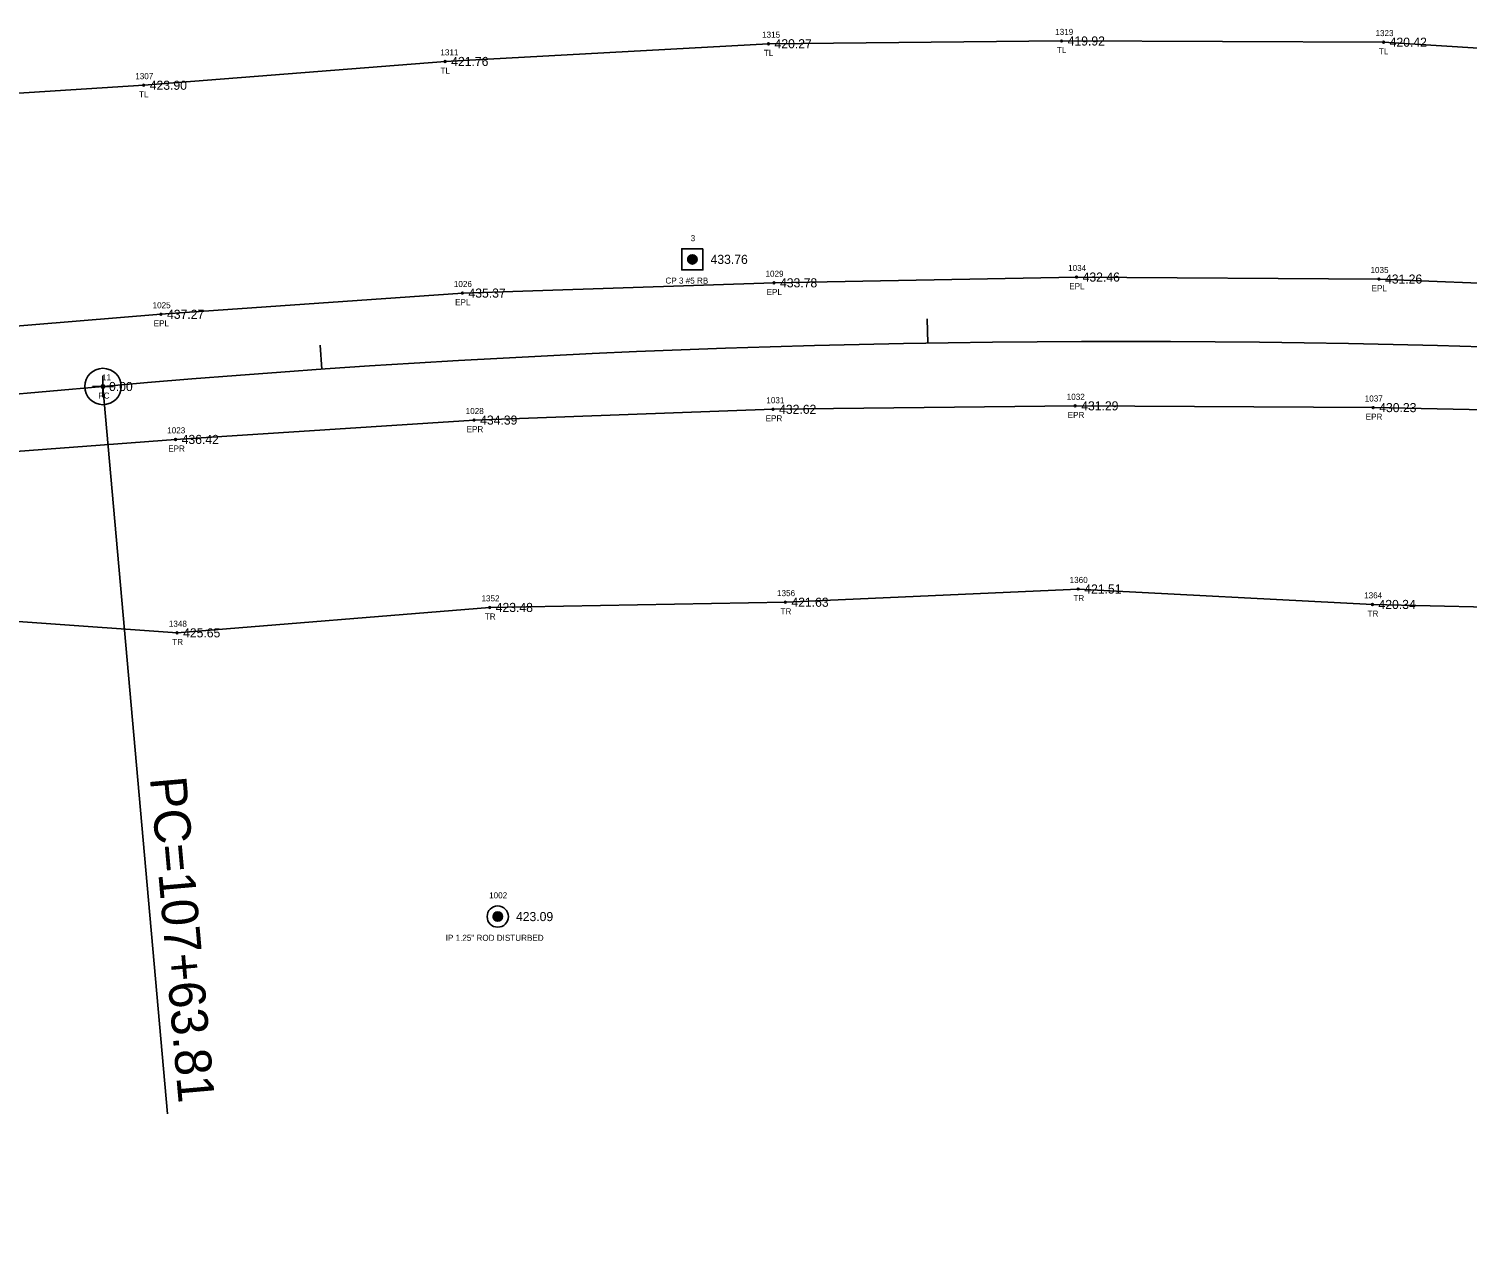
# Model space of a CAD drawing. Extents: x 1611114 to 1617038, y 769445 to 772083.
# Drawn here: x 1613520.1 to 1613757.2, y 771205.5 to 771408.3 of the extents above; entities that cross this region are included whole.
import ezdxf

# ---------------------------------------------------------------- set-up
doc = ezdxf.new("R2010")
doc.units = 0
for name, color, linetype in [('Default', 7, 'Continuous'), ('RD_EX_DV_Prop_txCode', 7, 'Continuous'), ('RD_EX_DV_PropPin', 7, 'Continuous'), ('RD_EX_Road', 7, 'Continuous'), ('RD_EX_Road_txCode', 7, 'Continuous'), ('RD_EX_TX_DV_Prop_ELEV', 7, 'Continuous'), ('RD_EX_TX_Road_ELEV', 7, 'Continuous'), ('RD_EX_TX_VEG_ELEV', 7, 'Continuous'), ('RD_EX_VEG', 7, 'Continuous'), ('RD_EX_VEG_txCode', 7, 'Continuous'), ('RD_HC_Cl', 7, 'Continuous'), ('RD_HC_Data', 7, 'Continuous'), ('RD_HC_Data_Tic', 7, 'Continuous'), ('RD_HC_Survey', 7, 'Continuous'), ('RD_HC_Survey_ELEV', 7, 'Continuous'), ('RD_HC_Survey_txCode', 7, 'Continuous'), ('RD_HC_txCode', 7, 'Continuous'), ('RD_SMD_Locator', 7, 'Continuous')]:
    doc.layers.add(name, color=color, linetype=linetype)

msp = doc.modelspace()

# ---------------------------------------------------------------- linework, layer by layer
at = {"layer": 'Default'}
for p, q in [((1612970.69, 771299.55), (1613532.3, 771349.3)), ((1613534.05, 771349.3), (1613530.55, 771349.3)), ((1613532.3, 771351.05), (1613532.3, 771347.55))]:
    msp.add_line(p, q, dxfattribs=at)
msp.add_arc((1613700.84, 769446.93), 1909.82, 80.96676, 95.06271, dxfattribs=at)
msp.add_arc((1613700.84, 769446.93), 1909.82, 80.96676, 95.06271, dxfattribs=at)
at = {"layer": 'RD_EX_DV_PropPin'}
for p, q in [((1613596.65, 771261.68), (1613596.65, 771262.07)), ((1613596.69, 771261.58), (1613596.69, 771262.17)), ((1613596.72, 771261.5), (1613596.72, 771262.24)), ((1613596.76, 771261.45), (1613596.76, 771262.3)), ((1613596.79, 771261.4), (1613596.79, 771262.35)), ((1613596.83, 771261.36), (1613596.83, 771262.39)), ((1613596.86, 771261.32), (1613596.86, 771262.42)), ((1613596.9, 771261.29), (1613596.9, 771262.46)), ((1613596.93, 771261.26), (1613596.93, 771262.48)), ((1613596.97, 771261.24), (1613596.97, 771262.51)), ((1613597, 771261.22), (1613597, 771262.53)), ((1613597.04, 771261.2), (1613597.04, 771262.55)), ((1613597.07, 771261.18), (1613597.07, 771262.57)), ((1613597.11, 771261.17), (1613597.11, 771262.58)), ((1613597.14, 771261.15), (1613597.14, 771262.59)), ((1613597.18, 771261.14), (1613597.18, 771262.6)), ((1613597.21, 771261.13), (1613597.21, 771262.61)), ((1613597.25, 771261.13), (1613597.25, 771262.62)), ((1613597.28, 771261.12), (1613597.28, 771262.63)), ((1613597.32, 771261.12), (1613597.32, 771262.63)), ((1613597.35, 771261.11), (1613597.35, 771262.63)), ((1613597.39, 771261.11), (1613597.39, 771262.63)), ((1613597.42, 771261.11), (1613597.42, 771262.63)), ((1613597.46, 771261.12), (1613597.46, 771262.63)), ((1613597.49, 771261.12), (1613597.49, 771262.63)), ((1613597.53, 771261.13), (1613597.53, 771262.62)), ((1613597.56, 771261.13), (1613597.56, 771262.61)), ((1613597.6, 771261.14), (1613597.6, 771262.6)), ((1613597.63, 771261.15), (1613597.63, 771262.59)), ((1613597.67, 771261.17), (1613597.67, 771262.58)), ((1613597.7, 771261.18), (1613597.7, 771262.57)), ((1613597.74, 771261.2), (1613597.74, 771262.55)), ((1613597.77, 771261.22), (1613597.77, 771262.53)), ((1613597.81, 771261.24), (1613597.81, 771262.51)), ((1613597.84, 771261.26), (1613597.84, 771262.48)), ((1613597.88, 771261.29), (1613597.88, 771262.46)), ((1613597.91, 771261.32), (1613597.91, 771262.42)), ((1613597.95, 771261.36), (1613597.95, 771262.39)), ((1613597.98, 771261.4), (1613597.98, 771262.35)), ((1613598.02, 771261.45), (1613598.02, 771262.3)), ((1613598.05, 771261.5), (1613598.05, 771262.24)), ((1613598.09, 771261.58), (1613598.09, 771262.17)), ((1613598.12, 771261.68), (1613598.12, 771262.07))]:
    msp.add_line(p, q, dxfattribs=at)
for radius in [1.75, 0.761]:
    msp.add_circle((1613597.39, 771261.87), radius, dxfattribs=at)
at = {"layer": 'RD_EX_Road'}
for points in [[(1613192.48, 771329.15), (1613292.05, 771338.23), (1613391, 771348.45), (1613492.61, 771357.17), (1613541.86, 771361.21), (1613591.56, 771364.71), (1613642.92, 771366.4), (1613692.81, 771367.35), (1613742.66, 771367.02), (1613792.19, 771365.04), (1613843.32, 771361.63), (1613887.78, 771357.57), (1613892.3, 771358.63)], [(1613194.6, 771309.27), (1613294.55, 771318.15), (1613393.75, 771328.31), (1613493.74, 771336.74), (1613544.27, 771340.57), (1613593.48, 771343.76), (1613642.77, 771345.54), (1613692.58, 771346.11), (1613741.71, 771345.82), (1613791.79, 771344.79), (1613840.79, 771341.46), (1613889.25, 771335.84)]]:
    msp.add_lwpolyline(points, dxfattribs=at)
at = {"layer": 'RD_EX_VEG'}
for points in [[(1613190.16, 771350.86), (1613289.21, 771359.12), (1613387.94, 771369.51), (1613489.82, 771379.95), (1613503.78, 771396.75), (1613539.01, 771398.99), (1613588.71, 771402.91), (1613642.02, 771405.83), (1613690.35, 771406.29), (1613743.43, 771406.09), (1613794.76, 771402.87), (1613849.1, 771400.75), (1613898.57, 771402.5), (1614071.38, 771363.76), (1614171, 771346.54), (1614270.56, 771328.42), (1614365.98, 771308.81), (1614467.36, 771290.78), (1614565.75, 771274.12), (1614666.78, 771259.85)], [(1613196.47, 771290.95), (1613297.34, 771299.06), (1613395.35, 771312.89), (1613495.9, 771312.14), (1613544.51, 771308.67), (1613596.05, 771312.86), (1613644.8, 771313.72), (1613693.08, 771315.9), (1613741.59, 771313.35), (1613789.13, 771312.23), (1613836.26, 771305.8), (1613884.78, 771289.64), (1614061.95, 771273.87), (1614158.04, 771264.13), (1614253.51, 771253.52), (1614356.63, 771247.59), (1614457.77, 771232.22), (1614557.61, 771219.54), (1614658.3, 771205.52)]]:
    msp.add_lwpolyline(points, dxfattribs=at)
at = {"layer": 'RD_HC_Cl'}
msp.add_line((1612970.69, 771299.55), (1613532.3, 771349.3), dxfattribs=at)
msp.add_arc((1613700.84, 769446.93), 1909.82, 80.96676, 95.06271, dxfattribs=at)
at = {"layer": 'RD_HC_Data'}
msp.add_line((1613532.3, 771349.3), (1613542.94, 771229.31), dxfattribs=at)
for radius in [3, 0.282]:
    msp.add_circle((1613532.3, 771349.3), radius, dxfattribs=at)
at = {"layer": 'RD_HC_Data_Tic'}
for p, q in [((1613668.27, 771356.47), (1613668.2, 771360.47)), ((1613568.38, 771352.15), (1613568.1, 771356.14))]:
    msp.add_line(p, q, dxfattribs=at)
at = {"layer": 'RD_HC_Survey'}
for p, q in [((1613628.72, 771370.09), (1613628.72, 771370.45)), ((1613628.75, 771370), (1613628.75, 771370.53)), ((1613628.77, 771369.94), (1613628.77, 771370.59)), ((1613628.8, 771369.9), (1613628.8, 771370.64)), ((1613628.82, 771369.85), (1613628.82, 771370.68)), ((1613628.85, 771369.82), (1613628.85, 771370.72)), ((1613628.87, 771369.78), (1613628.87, 771370.75)), ((1613628.89, 771369.75), (1613628.89, 771370.78)), ((1613628.92, 771369.73), (1613628.92, 771370.8)), ((1613628.94, 771369.7), (1613628.94, 771370.83)), ((1613628.97, 771369.68), (1613628.97, 771370.85)), ((1613628.99, 771369.66), (1613628.99, 771370.87)), ((1613629.02, 771369.64), (1613629.02, 771370.89)), ((1613629.04, 771369.63), (1613629.04, 771370.91)), ((1613629.07, 771369.61), (1613629.07, 771370.92)), ((1613629.09, 771369.6), (1613629.09, 771370.94)), ((1613629.12, 771369.58), (1613629.12, 771370.95)), ((1613629.14, 771369.57), (1613629.14, 771370.96)), ((1613629.17, 771369.56), (1613629.17, 771370.97)), ((1613629.19, 771369.55), (1613629.19, 771370.98)), ((1613629.22, 771369.54), (1613629.22, 771370.99)), ((1613629.24, 771369.53), (1613629.24, 771371)), ((1613629.27, 771369.52), (1613629.27, 771371.01)), ((1613629.29, 771369.52), (1613629.29, 771371.01)), ((1613629.32, 771369.51), (1613629.32, 771371.02)), ((1613629.34, 771369.51), (1613629.34, 771371.02)), ((1613629.37, 771369.5), (1613629.37, 771371.03)), ((1613629.39, 771369.5), (1613629.39, 771371.03)), ((1613629.41, 771369.5), (1613629.41, 771371.03)), ((1613629.44, 771369.5), (1613629.44, 771371.03)), ((1613629.46, 771369.5), (1613629.46, 771371.04)), ((1613629.49, 771369.5), (1613629.49, 771371.04)), ((1613629.51, 771369.5), (1613629.51, 771371.03)), ((1613629.54, 771369.5), (1613629.54, 771371.03)), ((1613629.56, 771369.5), (1613629.56, 771371.03)), ((1613629.59, 771369.51), (1613629.59, 771371.03)), ((1613629.61, 771369.51), (1613629.61, 771371.02)), ((1613629.64, 771369.52), (1613629.64, 771371.02)), ((1613629.66, 771369.52), (1613629.66, 771371.01)), ((1613629.69, 771369.53), (1613629.69, 771371)), ((1613629.71, 771369.54), (1613629.71, 771371)), ((1613629.74, 771369.54), (1613629.74, 771370.99)), ((1613629.76, 771369.55), (1613629.76, 771370.98)), ((1613629.79, 771369.56), (1613629.79, 771370.97)), ((1613629.81, 771369.58), (1613629.81, 771370.96)), ((1613629.84, 771369.59), (1613629.84, 771370.94)), ((1613629.86, 771369.6), (1613629.86, 771370.93)), ((1613629.88, 771369.62), (1613629.88, 771370.91)), ((1613629.91, 771369.63), (1613629.91, 771370.9)), ((1613629.93, 771369.65), (1613629.93, 771370.88)), ((1613629.96, 771369.67), (1613629.96, 771370.86)), ((1613629.98, 771369.69), (1613629.98, 771370.84)), ((1613630.01, 771369.72), (1613630.01, 771370.82)), ((1613630.03, 771369.74), (1613630.03, 771370.79)), ((1613630.06, 771369.77), (1613630.06, 771370.76)), ((1613630.08, 771369.8), (1613630.08, 771370.73)), ((1613630.11, 771369.84), (1613630.11, 771370.7)), ((1613630.13, 771369.87), (1613630.13, 771370.66)), ((1613630.16, 771369.92), (1613630.16, 771370.61)), ((1613630.18, 771369.97), (1613630.18, 771370.56)), ((1613630.21, 771370.04), (1613630.21, 771370.49)), ((1613630.23, 771370.15), (1613630.23, 771370.38))]:
    msp.add_line(p, q, dxfattribs=at)
msp.add_lwpolyline([(1613631.22, 771372.02), (1613627.72, 771372.02), (1613627.72, 771368.52), (1613631.22, 771368.52)], close=True, dxfattribs=at)
msp.add_circle((1613629.47, 771370.27), 0.769, dxfattribs=at)
at = {"layer": 'RD_SMD_Locator'}
for centre in [(1613642.02, 771405.83), (1613690.35, 771406.29), (1613743.43, 771406.09), (1613588.71, 771402.91), (1613539.01, 771398.99), (1613629.47, 771370.27), (1613642.92, 771366.4), (1613692.81, 771367.35), (1613742.66, 771367.02), (1613591.56, 771364.71), (1613541.86, 771361.21), (1613532.3, 771349.3), (1613642.77, 771345.54), (1613692.58, 771346.11), (1613741.71, 771345.82), (1613593.48, 771343.76), (1613544.27, 771340.57), (1613693.08, 771315.9), (1613644.8, 771313.72), (1613741.59, 771313.35), (1613596.05, 771312.86), (1613544.51, 771308.67), (1613597.39, 771261.87)]:
    msp.add_circle(centre, 0.15, dxfattribs=at)

# ---------------------------------------------------------------- texts
at = {"layer": 'RD_EX_DV_Prop_txCode'}
for s, p in [('1002', (1613595.96, 771264.87)), ('IP 1.25" ROD DISTURBED', (1613588.8, 771257.87))]:
    msp.add_text(s, height=1, dxfattribs=at).set_placement(p)
at = {"layer": 'RD_EX_Road_txCode'}
for s, p in [('1029', (1613641.53, 771367.4)), ('1034', (1613691.42, 771368.35)), ('1035', (1613741.27, 771368.02)), ('1026', (1613590.15, 771365.71)), ('EPL', (1613691.6, 771365.35)), ('EPL', (1613741.45, 771365.02)), ('1025', (1613540.48, 771362.21)), ('EPL', (1613590.36, 771362.71)), ('EPL', (1613641.71, 771364.4)), ('EPL', (1613540.66, 771359.21)), ('1031', (1613641.67, 771346.54)), ('1032', (1613691.19, 771347.11)), ('1037', (1613740.32, 771346.82)), ('1028', (1613592.1, 771344.76)), ('EPR', (1613641.55, 771343.54)), ('EPR', (1613691.35, 771344.11)), ('EPR', (1613740.48, 771343.82)), ('1023', (1613542.89, 771341.57)), ('EPR', (1613592.25, 771341.76)), ('EPR', (1613543.05, 771338.57))]:
    msp.add_text(s, height=1, dxfattribs=at).set_placement(p)
at = {"layer": 'RD_EX_TX_DV_Prop_ELEV'}
msp.add_text('423.09', height=1.5, dxfattribs=at).set_placement((1613600.39, 771261.12))
at = {"layer": 'RD_EX_TX_Road_ELEV'}
for s, p in [('432.46', (1613693.81, 771366.6)), ('433.78', (1613643.92, 771365.65)), ('431.26', (1613743.66, 771366.27)), ('435.37', (1613592.56, 771363.96)), ('437.27', (1613542.86, 771360.46)), ('431.29', (1613693.58, 771345.36)), ('430.23', (1613742.71, 771345.07)), ('434.39', (1613594.48, 771343.01)), ('432.62', (1613643.77, 771344.79)), ('436.42', (1613545.27, 771339.82))]:
    msp.add_text(s, height=1.5, dxfattribs=at).set_placement(p)
at = {"layer": 'RD_EX_TX_VEG_ELEV'}
for s, p in [('420.27', (1613643.02, 771405.08)), ('419.92', (1613691.35, 771405.54)), ('420.42', (1613744.43, 771405.34)), ('421.76', (1613589.71, 771402.16)), ('423.90', (1613540.01, 771398.24)), ('421.51', (1613694.08, 771315.15)), ('423.48', (1613597.05, 771312.11)), ('421.63', (1613645.8, 771312.97)), ('420.34', (1613742.59, 771312.6)), ('425.65', (1613545.51, 771307.92))]:
    msp.add_text(s, height=1.5, dxfattribs=at).set_placement(p)
at = {"layer": 'RD_EX_VEG_txCode'}
for s, p in [('1319', (1613689.29, 771407.29)), ('1315', (1613640.96, 771406.83)), ('1323', (1613742.09, 771407.09)), ('1311', (1613587.93, 771403.91)), ('TL', (1613641.25, 771403.83)), ('TL', (1613689.58, 771404.29)), ('TL', (1613742.66, 771404.09)), ('TL', (1613587.94, 771400.91)), ('1307', (1613537.62, 771399.99)), ('TL', (1613538.24, 771396.99)), ('1356', (1613643.43, 771314.72)), ('1360', (1613691.67, 771316.9)), ('1352', (1613594.7, 771313.86)), ('TR', (1613692.29, 771313.9)), ('1364', (1613740.22, 771314.35)), ('TR', (1613595.25, 771310.86)), ('TR', (1613644.01, 771311.72)), ('TR', (1613740.79, 771311.35)), ('1348', (1613543.16, 771309.67)), ('TR', (1613543.72, 771306.67))]:
    msp.add_text(s, height=1, dxfattribs=at).set_placement(p)
at = {"layer": 'RD_HC_Data'}
msp.add_text('PC=107+63.81', height=6, rotation=275.0627, dxfattribs=at).set_placement((1613540.03, 771284.73))
at = {"layer": 'RD_HC_Survey_ELEV'}
for s, p in [('433.76', (1613632.47, 771369.52)), ('0.00', (1613533.3, 771348.55))]:
    msp.add_text(s, height=1.5, dxfattribs=at).set_placement(p)
at = {"layer": 'RD_HC_Survey_txCode'}
for s, p in [('3', (1613629.19, 771373.27)), ('CP 3 #5 RB', (1613625.03, 771366.27))]:
    msp.add_text(s, height=1, dxfattribs=at).set_placement(p)
at = {"layer": 'RD_HC_txCode'}
for s, p in [('11', (1613532.14, 771350.3)), ('PC', (1613531.53, 771347.3))]:
    msp.add_text(s, height=1, dxfattribs=at).set_placement(p)

doc.saveas('drawing.dxf')
